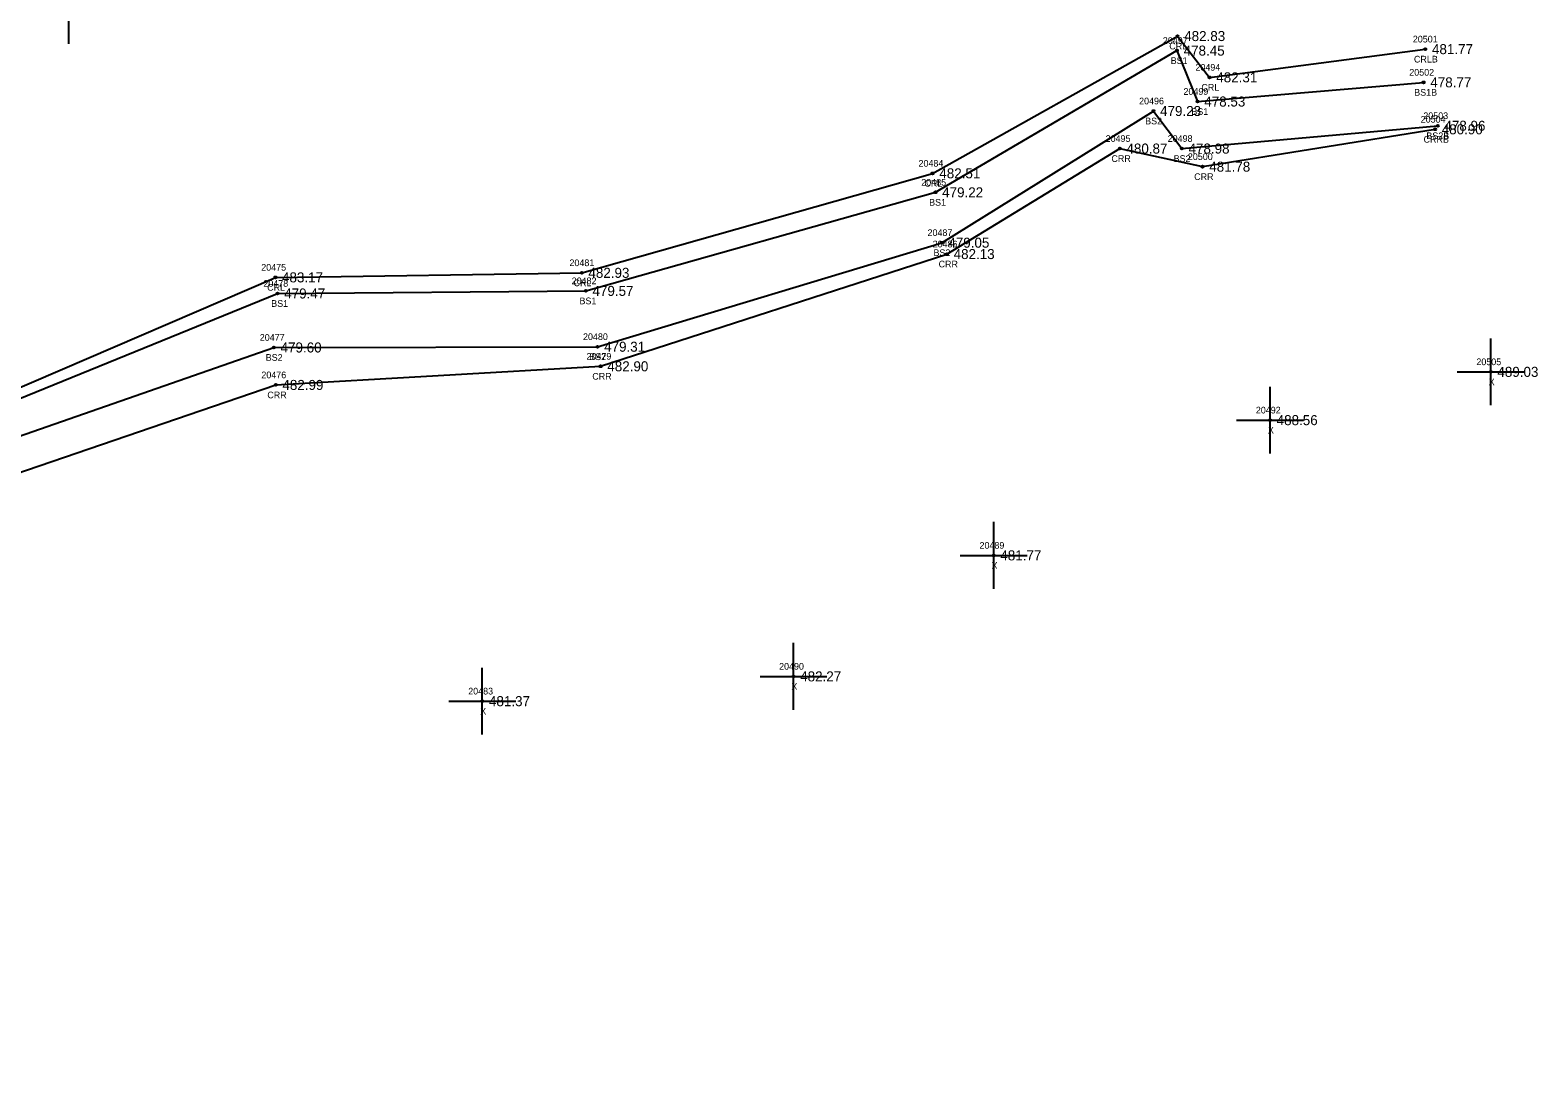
# Model space of a CAD drawing. Extents: x 1649406 to 1650436, y 896752 to 898178.
# Drawn here: x 1650210.2 to 1650435.8, y 897423.6 to 897580 of the extents above; entities that cross this region are included whole.
import ezdxf

# ---------------------------------------------------------------- set-up
doc = ezdxf.new("R2010")
doc.units = 0
for name, color, linetype in [('RD_DTM_BkLn2', 7, 'Continuous'), ('RD_DTM_BkLn_txCode', 7, 'Continuous'), ('RD_EX_H2O', 7, 'Continuous'), ('RD_EX_H2O_txCode', 7, 'Continuous'), ('RD_EX_Misc', 7, 'Continuous'), ('RD_EX_Misc_txCode', 7, 'Continuous'), ('RD_EX_TX_H2O_ELEV', 7, 'Continuous'), ('RD_EX_TX_Misc_ELEV', 7, 'Continuous'), ('RD_SMD_Locator', 7, 'Continuous')]:
    doc.layers.add(name, color=color, linetype=linetype)

msp = doc.modelspace()

# ---------------------------------------------------------------- linework, layer by layer
at = {"layer": 'RD_DTM_BkLn2'}
for points in [[(1649873.21, 897436.53), (1649903.52, 897432.72), (1649919.05, 897445.43), (1649948.16, 897462.25), (1649998.36, 897472.78), (1650066.66, 897490.8), (1650100.48, 897500.37), (1650137.22, 897517.85), (1650184.21, 897531.99), (1650196.44, 897519.92), (1650247.18, 897540.57), (1650293.31, 897540.96), (1650345.63, 897555.71), (1650381.77, 897576.92), (1650384.86, 897569.3), (1650418.68, 897572.17)], [(1649870.24, 897429.91), (1649900.86, 897426.65), (1649924.89, 897441.29), (1649954.5, 897454.17), (1650003.28, 897466.46), (1650067.47, 897482.78), (1650102.49, 897492.5), (1650136.77, 897511.64), (1650185.16, 897523.83), (1650191.93, 897513.41), (1650246.64, 897532.49), (1650295.05, 897532.6), (1650346.56, 897548.17), (1650378.24, 897567.88), (1650382.5, 897562.26), (1650420.79, 897565.67)]]:
    msp.add_lwpolyline(points, dxfattribs=at)
at = {"layer": 'RD_EX_H2O'}
for points in [[(1649876.68, 897438.74), (1649903.57, 897434.32), (1649917.97, 897448.25), (1649945.97, 897466.05), (1649997.07, 897475.13), (1650065.61, 897493.38), (1650098.97, 897502.84), (1650134.01, 897525.34), (1650184.58, 897534.43), (1650198.48, 897522.14), (1650246.85, 897542.98), (1650292.7, 897543.66), (1650345.21, 897558.55), (1650381.85, 897579.1), (1650386.65, 897572.92), (1650418.93, 897577.14)], [(1649868.27, 897424.7), (1649897.36, 897423.62), (1649925.96, 897437.78), (1649956.47, 897450.69), (1650000.97, 897459.86), (1650068.15, 897479.89), (1650103.08, 897490.82), (1650137.62, 897510.46), (1650180.41, 897516.6), (1650196.59, 897509.69), (1650246.91, 897526.88), (1650295.53, 897529.67), (1650347.35, 897546.47), (1650373.21, 897562.26), (1650385.6, 897559.55), (1650420.39, 897565.14)]]:
    msp.add_lwpolyline(points, dxfattribs=at)
at = {"layer": 'RD_EX_Misc'}
for p, q in [((1650215.93, 897577.91), (1650215.93, 897587.91)), ((1650428.72, 897523.84), (1650428.72, 897533.84)), ((1650423.72, 897528.84), (1650433.72, 897528.84)), ((1650395.69, 897516.61), (1650395.69, 897526.61)), ((1650390.69, 897521.61), (1650400.69, 897521.61)), ((1650354.34, 897496.37), (1650354.34, 897506.37)), ((1650349.34, 897501.37), (1650359.34, 897501.37)), ((1650324.39, 897478.26), (1650324.39, 897488.26)), ((1650277.82, 897474.55), (1650277.82, 897484.55)), ((1650319.39, 897483.26), (1650329.39, 897483.26)), ((1650272.82, 897479.55), (1650282.82, 897479.55))]:
    msp.add_line(p, q, dxfattribs=at)
at = {"layer": 'RD_SMD_Locator'}
for centre in [(1650381.85, 897579.1), (1650381.77, 897576.92), (1650418.93, 897577.14), (1650386.65, 897572.92), (1650418.68, 897572.17), (1650384.86, 897569.3), (1650378.24, 897567.88), (1650420.39, 897565.14), (1650420.79, 897565.67), (1650373.21, 897562.26), (1650382.5, 897562.26), (1650345.21, 897558.55), (1650385.6, 897559.55), (1650345.63, 897555.71), (1650346.56, 897548.17), (1650347.35, 897546.47), (1650246.85, 897542.98), (1650292.7, 897543.66), (1650247.18, 897540.57), (1650293.31, 897540.96), (1650246.64, 897532.49), (1650295.05, 897532.6), (1650295.53, 897529.67), (1650428.72, 897528.84), (1650246.91, 897526.88), (1650395.69, 897521.61), (1650354.34, 897501.37), (1650324.39, 897483.26), (1650277.82, 897479.55)]:
    msp.add_circle(centre, 0.15, dxfattribs=at)

# ---------------------------------------------------------------- texts
at = {"layer": 'RD_DTM_BkLn_txCode'}
for s, p in [('20497', (1650379.65, 897577.92)), ('BS1', (1650380.83, 897574.92)), ('20502', (1650416.53, 897573.17)), ('20499', (1650382.74, 897570.3)), ('20496', (1650376.1, 897568.88)), ('BS1B', (1650417.27, 897570.17)), ('BS2', (1650377.01, 897565.88)), ('BS1', (1650383.92, 897567.3)), ('20503', (1650418.63, 897566.67)), ('BS2B', (1650419.09, 897563.67)), ('20498', (1650380.38, 897563.26)), ('BS2', (1650381.27, 897560.26)), ('20485', (1650343.51, 897556.71)), ('BS1', (1650344.68, 897553.71)), ('20487', (1650344.44, 897549.17)), ('BS2', (1650345.33, 897546.17)), ('20478', (1650245.06, 897541.57)), ('20482', (1650291.19, 897541.96)), ('BS1', (1650292.36, 897538.96)), ('BS1', (1650246.23, 897538.57)), ('20477', (1650244.52, 897533.49)), ('20480', (1650292.89, 897533.6)), ('BS2', (1650245.41, 897530.49)), ('BS2', (1650293.82, 897530.6))]:
    msp.add_text(s, height=1, dxfattribs=at).set_placement(p)
at = {"layer": 'RD_EX_H2O_txCode'}
for s, p in [('CRL', (1650380.62, 897577.1)), ('20501', (1650417.06, 897578.14)), ('CRLB', (1650417.23, 897575.14)), ('20494', (1650384.53, 897573.92)), ('CRL', (1650385.42, 897570.92)), ('20504', (1650418.24, 897566.14)), ('20495', (1650371.09, 897563.26)), ('CRRB', (1650418.67, 897563.14)), ('20484', (1650343.09, 897559.55)), ('CRR', (1650371.96, 897560.26)), ('20500', (1650383.4, 897560.55)), ('CRR', (1650384.34, 897557.55)), ('CRL', (1650343.98, 897556.55)), ('20486', (1650345.21, 897547.47)), ('20475', (1650244.74, 897543.98)), ('20481', (1650290.86, 897544.66)), ('CRR', (1650346.1, 897544.47)), ('CRL', (1650245.63, 897540.98)), ('CRL', (1650291.47, 897541.66)), ('20479', (1650293.41, 897530.67)), ('20476', (1650244.76, 897527.88)), ('CRR', (1650294.28, 897527.67)), ('CRR', (1650245.65, 897524.88))]:
    msp.add_text(s, height=1, dxfattribs=at).set_placement(p)
at = {"layer": 'RD_EX_Misc_txCode'}
for s, p in [('20505', (1650426.57, 897529.84)), ('X', (1650428.41, 897526.84)), ('20492', (1650393.57, 897522.61)), ('X', (1650395.38, 897519.61)), ('20489', (1650352.22, 897502.37)), ('X', (1650354.02, 897499.37)), ('20490', (1650322.23, 897484.26)), ('20483', (1650275.71, 897480.55)), ('X', (1650324.07, 897481.26)), ('X', (1650277.51, 897477.55))]:
    msp.add_text(s, height=1, dxfattribs=at).set_placement(p)
at = {"layer": 'RD_EX_TX_H2O_ELEV'}
for s, p in [('482.83', (1650382.85, 897578.35)), ('481.77', (1650419.93, 897576.39)), ('482.31', (1650387.65, 897572.17)), ('480.90', (1650421.39, 897564.39)), ('480.87', (1650374.21, 897561.51)), ('481.78', (1650386.6, 897558.8)), ('482.51', (1650346.21, 897557.8)), ('482.13', (1650348.35, 897545.72)), ('482.93', (1650293.7, 897542.91)), ('483.17', (1650247.85, 897542.23)), ('482.90', (1650296.53, 897528.92)), ('482.99', (1650247.91, 897526.13))]:
    msp.add_text(s, height=1.5, dxfattribs=at).set_placement(p)
at = {"layer": 'RD_EX_TX_Misc_ELEV'}
for s, p in [('478.45', (1650382.77, 897576.17)), ('478.77', (1650419.68, 897571.42)), ('478.53', (1650385.86, 897568.55)), ('479.23', (1650379.24, 897567.13)), ('478.96', (1650421.79, 897564.92)), ('478.98', (1650383.5, 897561.51)), ('479.22', (1650346.63, 897554.96)), ('479.05', (1650347.56, 897547.42)), ('479.47', (1650248.18, 897539.82)), ('479.57', (1650294.31, 897540.21)), ('479.60', (1650247.64, 897531.74)), ('479.31', (1650296.05, 897531.85)), ('489.03', (1650429.72, 897528.09)), ('488.56', (1650396.69, 897520.86)), ('481.77', (1650355.34, 897500.62)), ('482.27', (1650325.39, 897482.51)), ('481.37', (1650278.82, 897478.8))]:
    msp.add_text(s, height=1.5, dxfattribs=at).set_placement(p)

doc.saveas('drawing.dxf')
